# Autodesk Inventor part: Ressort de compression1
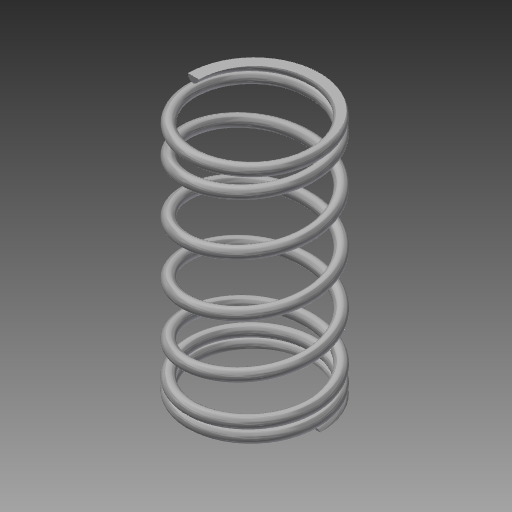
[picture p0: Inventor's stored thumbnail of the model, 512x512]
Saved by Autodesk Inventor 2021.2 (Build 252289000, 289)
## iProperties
CustomPartVersion: 1
Created: 2018-06
Part Number: Ressort de compression1
Material: Steel
Document SubType Name: Modeling
Designer: Fabian Perrée
Density: 2.18 g/cm^3
Appearance: Steel
Author: Fabian Perrée
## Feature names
1. Main Coil Feature(R)
2. Bobine de transition de départ 1 (droite)
3. Coil  Start Transition 2(R)
4. Coil  Start Transition 3(R)
5. Coil  Start Transition 4(R)
6. Bobine des extrémités de départ (droite)
7. Fonction de coupe de départ [Extrusion]
8. Bobine de transition de fin 1 (droite)
9. Bobine de transition de fin 2 (droite)
10. Bobine de transition de fin 3 (droite)
11. Bobine de transition de fin 4 (droite)
12. Bobine de fin (droite)
13. Fonction de coupe de fin (droite) [Extrusion]
14. Fonction de coupe à extrémités lisses (droite) [Extrusion]
15. Plain Ends Cut  2(R) [Extrusion]
16. Main Coil Feature(L)
17. Bobine de transition de départ 1 (gauche)
18. Bobine de transition de départ 2 (gauche)
19. Bobine de transition de départ 3 (gauche)
20. Bobine de transition de départ 4 (gauche)
21. Bobine de extrémités de départ (gauche)
22. Fonction de coupe de départ (gauche) [Extrusion]
23. Bobine de transition de fin 1 (gauche)
24. Bobine de transition de fin 2 (gauche)
25. Bobine de transition de fin 3 (gauche)
26. Bobine de transition de fin 4 (gauche)
27. Bobine de fin (gauche)
28. Fonction de coupe de fin (gauche) [Extrusion]
29. Cut Plain Ends Cut 1(L) [Extrusion]
30. Cut Plain Ends Cut 2(L) [Extrusion]
## Parameters: d0 = 0.125 mm, da_d = 0.5 mm, da_D2 = 5 mm, da_ti = 2.38768 mm, da_nz1 = 15 mm, spiral_Angle = 1.37316 mm, d2 = 2.38768 mm, d4 = 32.5 mm, d5 = 0, d6 = 90 deg, d7 = 90 deg, d8 = 0, d9 = 0, d12 = 1.40593 mm, d13 = -1.83409 mm, d14 = 0.5 mm, d15 = 0, d16 = 1.91576 mm, d18 = 2.5 mm, d19 = 0, d20 = 90 deg, d21 = 90 deg, d22 = 0, d23 = 0, d24 = 1.44384 mm, d26 = 2.5 mm, d27 = 0, d28 = 90 deg, d29 = 90 deg, d30 = 0, d31 = 0, d32 = 0.97192 mm, d34 = 2.5 mm, d35 = 0, d36 = 90 deg, d37 = 90 deg, d38 = 0, d39 = 0, d40 = 0.5 mm, d42 = 2.5 mm, d43 = 0, d44 = 90 deg, d45 = 90 deg, d46 = 0, d47 = 0, d48 = 1.91576 mm, d50 = 1.875 mm, d51 = 0, d52 = 90 deg, d53 = 90 deg, d54 = 0, d55 = 0, d56 = 1.44384 mm, d58 = 1.875 mm, d59 = 0, d60 = 90 deg, d61 = 90 deg, d62 = 0, d63 = 0, d64 = 0.97192 mm, d66 = 1.875 mm, d67 = 0, d68 = 90 deg, d69 = 90 deg, d70 = 0, d71 = 0, d72 = 0.5 mm, d74 = 1.875 mm, d75 = 0, d76 = 90 deg, d77 = 90 deg, d78 = 0, d79 = 0, End_Pitch = 0.50475 mm, d82 = 15 mm, d83 = 0, d84 = 90 deg, d85 = 90 deg, d86 = 0, d87 = 0, d88 = 0.50475 mm, d91 = 0, d92 = 90 deg, d93 = 90 deg, d94 = 0, d95 = 0, d96 = 6 mm, d97 = 0.50475 mm, d98 = 0, d99 = 6 mm, d100 = 0.50475 mm, d101 = 0, d102 = 0, d103 = 0, d104 = 0, d105 = 0, d106 = 0, d108 = 0, d112 = 0, d113 = 0, d114 = 0, const_zero = 0, Not_rightdir = 0, d121 = 0.13092 mm, d131 = 0, d132 = 0, d133 = 0, d134 = 0, d135 = 0.125 mm, d137 = 2.38768 mm, d139 = 32.5 mm, d140 = 0, d141 = 90 deg, d142 = 90 deg, d143 = 0, d144 = 0, d145 = 1.40593 mm, d146 = -1.83409 mm, d147 = 0.13092 mm, d148 = 0.00473 mm, d149 = 0.5 mm, d150 = 0, d151 = 0, d152 = 1.91576 mm, d154 = 2.5 mm, d155 = 0, d156 = 90 deg, d157 = 90 deg, d158 = 0, d159 = 0, d160 = 1.44384 mm, d162 = 2.5 mm, d163 = 0, d164 = 90 deg, d165 = 90 deg, d166 = 0, d167 = 0, d168 = 0.97192 mm, d170 = 2.5 mm, d171 = 0, d172 = 90 deg, d173 = 90 deg, d174 = 0, d175 = 0, d176 = 0.5 mm, d178 = 2.5 mm, d179 = 0, d180 = 90 deg, d181 = 90 deg, d182 = 0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
